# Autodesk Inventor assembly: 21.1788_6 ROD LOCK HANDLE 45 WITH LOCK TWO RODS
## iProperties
Created: 2007-03
Part Number: 21.1788_6 ROD LOCK HANDLE 45 WITH LOCK TWO RODS
Document SubType Name: Assembly
Designer: Andy Moles
Author: Andy Moles
